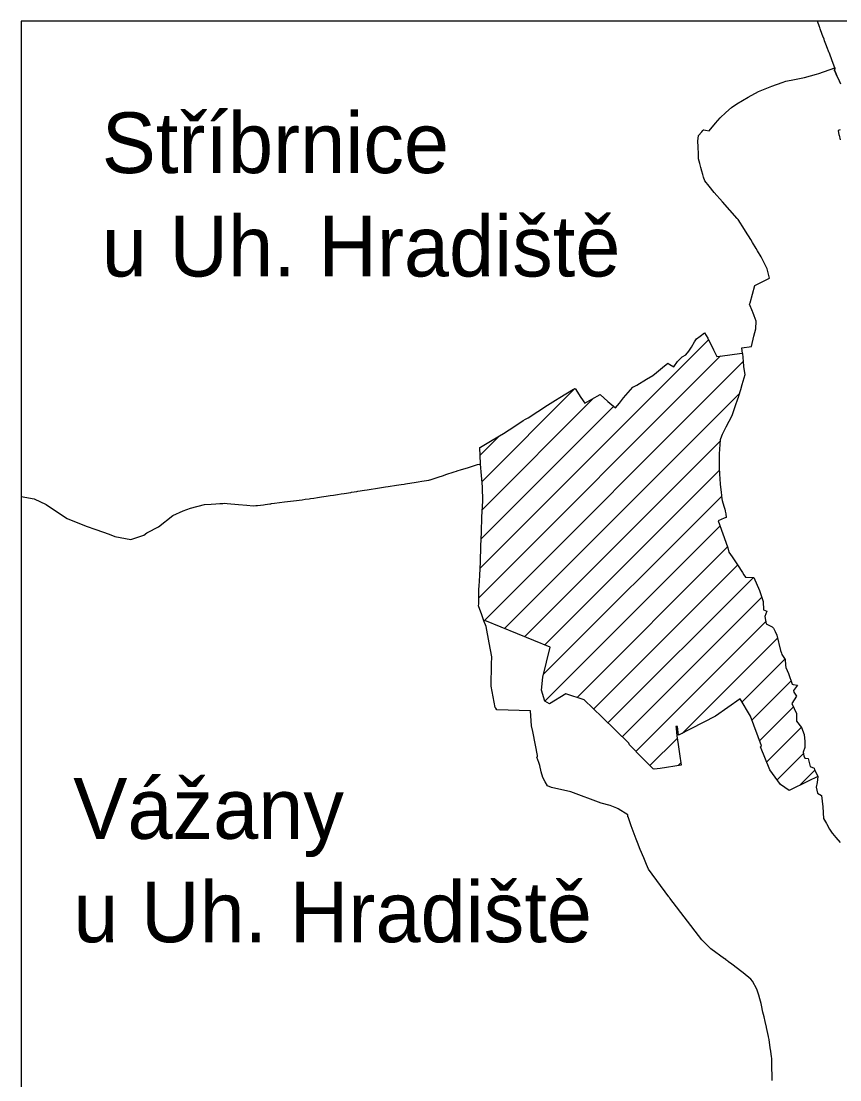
# Model space of a CAD drawing. Extents: x -552716 to -540720, y -1192685 to -1177912.
# Drawn here: x -549696 to -547852, y -1183546 to -1181162 of the extents above; entities that cross this region are included whole.
import ezdxf

# ---------------------------------------------------------------- set-up
doc = ezdxf.new("R2010")
doc.units = 0
for name, color, linetype in [('Default', 7, 'Continuous'), ('Vrstva 1', 7, 'Continuous'), ('Vrstva 2', 7, 'Continuous'), ('Vrstva 60', 7, 'Continuous')]:
    doc.layers.add(name, color=color, linetype=linetype)

msp = doc.modelspace()

# ---------------------------------------------------------------- linework, layer by layer
at = {"layer": 'Default'}
msp.add_lwpolyline([(-547901.8, -1182862.6), (-547923.2, -1182873.4), (-547966, -1182893.9), (-547985.6, -1182880.7), (-548010, -1182847.4), (-548031.1, -1182795.7), (-548028.8, -1182793.3), (-548053.4, -1182726.7), (-548076.4, -1182687.9), (-548132.3, -1182726.7), (-548215.2, -1182769.8), (-548218.1, -1182749.8), (-548221.7, -1182750.2), (-548221, -1182754.5), (-548219.1, -1182770.9), (-548216.5, -1182790.8), (-548213.3, -1182811.2), (-548209.2, -1182837.1), (-548256.6, -1182844.3), (-548270.4, -1182846.4), (-548272.9, -1182845), (-548301.7, -1182816.4), (-548320, -1182797.1), (-548326, -1182791.2), (-548327.3, -1182787.7), (-548387.7, -1182728.9), (-548427.9, -1182689.6), (-548469.4, -1182676.1), (-548506.2, -1182699.2), (-548516.9, -1182692.6), (-548523.7, -1182668.5), (-548521.4, -1182638.6), (-548504.5, -1182571.2), (-548651.4, -1182511.1), (-548653.6, -1182512)], dxfattribs=at)
at = {"layer": 'Vrstva 1'}
for p, q in [((-548174.9, -1181877), (-548166.9, -1181870.7)), ((-548166.9, -1181870.7), (-548156.9, -1181863.4)), ((-548156.9, -1181863.4), (-548149.3, -1181875.6)), ((-548186.4, -1181895.9), (-548179.2, -1181883.6)), ((-548179.2, -1181883.6), (-548174.9, -1181877)), ((-548149.3, -1181875.6), (-548136.5, -1181901.7)), ((-548217.8, -1181927.7), (-548207.2, -1181917.2)), ((-548207.2, -1181917.2), (-548199.2, -1181912.8)), ((-548199.2, -1181912.8), (-548192.1, -1181904.8)), ((-548192.1, -1181904.8), (-548186.4, -1181895.9)), ((-548136.5, -1181901.7), (-548129.2, -1181916.9)), ((-548129.2, -1181916.9), (-548121.7, -1181915.7)), ((-548121.7, -1181915.7), (-548073, -1181909.6)), ((-548073, -1181909.6), (-548071.3, -1181910)), ((-548071.3, -1181910), (-548069.8, -1181927.9)), ((-548265.3, -1181952.9), (-548251.9, -1181941.4)), ((-548251.9, -1181941.4), (-548239.4, -1181931.7)), ((-548239.4, -1181931.7), (-548235, -1181934.5)), ((-548235, -1181934.5), (-548226.1, -1181940.1)), ((-548226.1, -1181940.1), (-548217.8, -1181927.7)), ((-548069.8, -1181927.9), (-548068.9, -1181939.1)), ((-548068.9, -1181939.1), (-548066.3, -1181958.3)), ((-548287.2, -1181967.9), (-548273.5, -1181959.3)), ((-548273.5, -1181959.3), (-548265.3, -1181952.9)), ((-548066.3, -1181958.3), (-548072.7, -1181980.3)), ((-548451.7, -1181990.3), (-548448.3, -1181988.9)), ((-548448.3, -1181988.9), (-548435.2, -1182008.9)), ((-548329.1, -1181998), (-548318.1, -1181986.2)), ((-548318.1, -1181986.2), (-548309.3, -1181981.1)), ((-548309.3, -1181981.1), (-548287.2, -1181967.9)), ((-548072.7, -1181980.3), (-548076.1, -1181991.8)), ((-548492.4, -1182015.1), (-548482.7, -1182009.4)), ((-548482.7, -1182009.4), (-548469.2, -1182000.9)), ((-548469.2, -1182000.9), (-548451.7, -1181990.3)), ((-548435.2, -1182008.9), (-548426.1, -1182021.7)), ((-548426.1, -1182021.7), (-548410.5, -1182012.8)), ((-548410.5, -1182012.8), (-548391.6, -1182002.5)), ((-548391.6, -1182002.5), (-548374.7, -1182018.1)), ((-548348.6, -1182021.7), (-548339.1, -1182009.7)), ((-548339.1, -1182009.7), (-548329.1, -1181998)), ((-548082.5, -1182013), (-548087.6, -1182027.9)), ((-548081.1, -1182008.9), (-548082.5, -1182013)), ((-548080.3, -1182006.3), (-548081.1, -1182008.9)), ((-548076.1, -1181991.8), (-548080.3, -1182006.3)), ((-548532.2, -1182040.6), (-548510.7, -1182026.7)), ((-548510.7, -1182026.7), (-548492.4, -1182015.1)), ((-548374.7, -1182018.1), (-548357.4, -1182032.7)), ((-548357.4, -1182032.7), (-548348.6, -1182021.7)), ((-548087.6, -1182027.9), (-548095.3, -1182050.1)), ((-548579.7, -1182070.6), (-548565.1, -1182060.7)), ((-548565.1, -1182060.7), (-548559.8, -1182057.8)), ((-548559.8, -1182057.8), (-548553.8, -1182055)), ((-548553.8, -1182055), (-548532.2, -1182040.6)), ((-548095.3, -1182050.1), (-548108.9, -1182076.1)), ((-548609.9, -1182090.1), (-548597.1, -1182082.1)), ((-548597.1, -1182082.1), (-548579.7, -1182070.6)), ((-548109.6, -1182077.6), (-548117.3, -1182092.2)), ((-548108.9, -1182076.1), (-548109.6, -1182077.6)), ((-548661.6, -1182120.6), (-548639.3, -1182107.7)), ((-548639.3, -1182107.7), (-548618.3, -1182095.2)), ((-548618.3, -1182095.2), (-548609.9, -1182090.1)), ((-548121.6, -1182104.4), (-548123.7, -1182136.3)), ((-548120.8, -1182102.1), (-548121.6, -1182104.4)), ((-548117.3, -1182092.2), (-548120.8, -1182102.1)), ((-548663.3, -1182121.6), (-548661.6, -1182120.6)), ((-548661.5, -1182158.2), (-548663.3, -1182121.6)), ((-548123.7, -1182136.3), (-548123.7, -1182137.4)), ((-548123.7, -1182137.4), (-548123.6, -1182165.3)), ((-548661.4, -1182159.5), (-548661.5, -1182158.2)), ((-548656.7, -1182210.4), (-548661.4, -1182159.5)), ((-548123.6, -1182165.3), (-548123.6, -1182166.5)), ((-548123.6, -1182166.5), (-548122.9, -1182182.4)), ((-548122.9, -1182182.4), (-548122.4, -1182191.2)), ((-548122.4, -1182191.2), (-548121.5, -1182205.4)), ((-548656.3, -1182242.9), (-548656.7, -1182210.4)), ((-548121.5, -1182205.4), (-548119.6, -1182222.6)), ((-548119.6, -1182222.6), (-548118, -1182237.4)), ((-548658.2, -1182278.1), (-548656.3, -1182242.9)), ((-548118, -1182237.4), (-548117.1, -1182240.7)), ((-548117.1, -1182240.7), (-548113.7, -1182254.2)), ((-548113.7, -1182254.2), (-548111.5, -1182260.5)), ((-548111.5, -1182260.5), (-548110.5, -1182264)), ((-548110.5, -1182264), (-548110.1, -1182265.3)), ((-548110.1, -1182265.3), (-548109.2, -1182270.8)), ((-548109.2, -1182270.8), (-548107.8, -1182279.1)), ((-548659, -1182312.3), (-548658.2, -1182278.1)), ((-548112.4, -1182281.1), (-548125.8, -1182286.7)), ((-548125.8, -1182286.7), (-548105.2, -1182345.6)), ((-548107.8, -1182279.1), (-548112.4, -1182281.1)), ((-548660.4, -1182344), (-548659, -1182312.3)), ((-548661.7, -1182379.5), (-548660.4, -1182344)), ((-548105.2, -1182345.6), (-548104.7, -1182347.3)), ((-548104.7, -1182347.3), (-548101.8, -1182357.4)), ((-548101.8, -1182357.4), (-548094.7, -1182368.1)), ((-548094.7, -1182368.1), (-548082.8, -1182386.3)), ((-548663.3, -1182410.2), (-548661.7, -1182379.5)), ((-548082.8, -1182386.3), (-548071.6, -1182403.4)), ((-548664.8, -1182433.7), (-548663.3, -1182410.2)), ((-548071.6, -1182403.4), (-548068.2, -1182408.4)), ((-548068.2, -1182408.4), (-548064.5, -1182413.6)), ((-548064.5, -1182413.6), (-548045.5, -1182414.5)), ((-548045.5, -1182414.5), (-548032.9, -1182443.7)), ((-548665.1, -1182474.1), (-548664.9, -1182440.9)), ((-548664.9, -1182440.9), (-548664.8, -1182433.7)), ((-548032.9, -1182443.7), (-548024.6, -1182468.7)), ((-548665.6, -1182478.6), (-548665.1, -1182474.1)), ((-548658.8, -1182498.9), (-548665.6, -1182478.6)), ((-548024.6, -1182468.7), (-548024.1, -1182487.1)), ((-548024.1, -1182487.1), (-548016.9, -1182490.4)), ((-548016.9, -1182490.4), (-548021, -1182502.3)), ((-548653.6, -1182512), (-548658.8, -1182498.9)), ((-548648.7, -1182524.6), (-548653.6, -1182512)), ((-548021, -1182502.3), (-548018.1, -1182518.6)), ((-548641.7, -1182561.3), (-548648.7, -1182524.6)), ((-548018.1, -1182518.6), (-548004.5, -1182525.3)), ((-548004.5, -1182525.3), (-548001.6, -1182528.4)), ((-548001.6, -1182528.4), (-547997.4, -1182536.4)), ((-547997.4, -1182536.4), (-547994.1, -1182544)), ((-548635.9, -1182593.4), (-548641.7, -1182561.3)), ((-547994.1, -1182544), (-547986.1, -1182579.1)), ((-547986.1, -1182579.1), (-547983.8, -1182584.6)), ((-547983.8, -1182584.6), (-547982.5, -1182587.9)), ((-548637.6, -1182658.9), (-548636.5, -1182609.9)), ((-548636.5, -1182609.9), (-548635.9, -1182593.4)), ((-547982.5, -1182587.9), (-547974.9, -1182598.9)), ((-547974.9, -1182598.9), (-547974.6, -1182612)), ((-547974.6, -1182612), (-547973.4, -1182617.2)), ((-547973.4, -1182617.2), (-547967.7, -1182630.5)), ((-547967.7, -1182630.5), (-547959.2, -1182654.4)), ((-547959.2, -1182654.4), (-547956.9, -1182655.4)), ((-547956.9, -1182655.4), (-547947.5, -1182656.8)), ((-547947.5, -1182656.8), (-547956.1, -1182669.3)), ((-548628.2, -1182707.3), (-548637.6, -1182658.9)), ((-547956.1, -1182669.3), (-547955.4, -1182673)), ((-547955.4, -1182673), (-547949.7, -1182681.7)), ((-547949.7, -1182681.7), (-547960.2, -1182698)), ((-547960.2, -1182698), (-547949.5, -1182721)), ((-548627, -1182709.1), (-548628.2, -1182707.3)), ((-548624.7, -1182712.5), (-548627, -1182709.1)), ((-548549.2, -1182715.1), (-548624.7, -1182712.5)), ((-548546.3, -1182748.6), (-548549.2, -1182715.1)), ((-547949.5, -1182721), (-547950, -1182738.2)), ((-548543.8, -1182761.5), (-548546.3, -1182748.6)), ((-547950, -1182738.2), (-547938.6, -1182752.1)), ((-547938.6, -1182752.1), (-547932.4, -1182767.7)), ((-548537.8, -1182792.2), (-548543.8, -1182761.5)), ((-547932.4, -1182767.7), (-547930.7, -1182783.5)), ((-548533.2, -1182815.6), (-548537.8, -1182792.2)), ((-547930.6, -1182797.2), (-547934.8, -1182807.6)), ((-547930.7, -1182783.5), (-547930.6, -1182797.2)), ((-548534.4, -1182819), (-548532.8, -1182817.7)), ((-548529.8, -1182831.3), (-548534.4, -1182819)), ((-548532.8, -1182817.7), (-548533.2, -1182815.6)), ((-547934.8, -1182807.6), (-547932.9, -1182816.1)), ((-547932.9, -1182816.1), (-547931, -1182821.2)), ((-547931, -1182821.2), (-547923.5, -1182822.4)), ((-547923.5, -1182822.4), (-547918.7, -1182840.1)), ((-548528.1, -1182838.1), (-548529.8, -1182831.3)), ((-548524.5, -1182852.3), (-548528.1, -1182838.1)), ((-547918.7, -1182840.1), (-547909.7, -1182843.6)), ((-547909.7, -1182843.6), (-547909.3, -1182846.6)), ((-547909.3, -1182846.6), (-547901.8, -1182862.6)), ((-548521.2, -1182865.1), (-548524.5, -1182852.3)), ((-548515.9, -1182874.6), (-548521.2, -1182865.1)), ((-547901.8, -1182862.6), (-547903.4, -1182876)), ((-548510.8, -1182883.7), (-548515.9, -1182874.6)), ((-548501.2, -1182887.3), (-548510.8, -1182883.7)), ((-548458, -1182897.5), (-548501.2, -1182887.3)), ((-547903.4, -1182876), (-547905.3, -1182886.7)), ((-547905.3, -1182886.7), (-547902.5, -1182900.1)), ((-548389.9, -1182922.6), (-548458, -1182897.5)), ((-547902.5, -1182900.1), (-547893.5, -1182905.3)), ((-547893.5, -1182905.3), (-547890.7, -1182930.9)), ((-548369.1, -1182928.1), (-548389.9, -1182922.6)), ((-548354.7, -1182933.8), (-548369.1, -1182928.1)), ((-548351.3, -1182935.1), (-548354.7, -1182933.8)), ((-548329.4, -1182948.9), (-548351.3, -1182935.1)), ((-547890.7, -1182930.9), (-547888.6, -1182957)), ((-548329.4, -1182953.3), (-548329.4, -1182948.9)), ((-548329.2, -1182953.8), (-548329.4, -1182953.3)), ((-548322, -1182973.8), (-548329.2, -1182953.8)), ((-547888.6, -1182957), (-547882.4, -1182968.1)), ((-548315.5, -1182991.8), (-548322, -1182973.8)), ((-547882.4, -1182968.1), (-547881.4, -1182969.9)), ((-547881.4, -1182969.9), (-547875.1, -1182981.3)), ((-547875.1, -1182981.3), (-547869.5, -1182990)), ((-547869.5, -1182990), (-547868.6, -1182991.2)), ((-547868.6, -1182991.2), (-547861.3, -1183000.1)), ((-548311.1, -1183004), (-548315.5, -1182991.8)), ((-548308.2, -1183010.9), (-548311.1, -1183004)), ((-548301.5, -1183027), (-548308.2, -1183010.9)), ((-547861.3, -1183000.1), (-547851.6, -1183011.3)), ((-548293.9, -1183045.5), (-548301.5, -1183027)), ((-548287.6, -1183060.6), (-548293.9, -1183045.5)), ((-548283.2, -1183071.2), (-548287.6, -1183060.6)), ((-548237.1, -1183133.7), (-548283.2, -1183071.2)), ((-548235.9, -1183135.3), (-548237.1, -1183133.7)), ((-548235, -1183136.5), (-548235.9, -1183135.3)), ((-548162.7, -1183230.2), (-548235, -1183136.5)), ((-548142.7, -1183251), (-548162.7, -1183230.2)), ((-548111.8, -1183272.9), (-548142.7, -1183251)), ((-548111.2, -1183273.3), (-548111.8, -1183272.9)), ((-548109.2, -1183274.9), (-548111.2, -1183273.3)), ((-548108.9, -1183275.1), (-548109.2, -1183274.9)), ((-548104.6, -1183278.3), (-548108.9, -1183275.1)), ((-548103.4, -1183279.3), (-548104.6, -1183278.3)), ((-548102.7, -1183279.8), (-548103.4, -1183279.3)), ((-548095.2, -1183285.5), (-548102.7, -1183279.8)), ((-548072.9, -1183302.4), (-548095.2, -1183285.5)), ((-548069.6, -1183304.9), (-548072.9, -1183302.4)), ((-548052.8, -1183319.2), (-548069.6, -1183304.9)), ((-548048.8, -1183323.6), (-548052.8, -1183319.2)), ((-548039.2, -1183341.9), (-548048.8, -1183323.6)), ((-548036.2, -1183350.4), (-548039.2, -1183341.9)), ((-548034.5, -1183355.3), (-548036.2, -1183350.4)), ((-548032.3, -1183363.6), (-548034.5, -1183355.3)), ((-548029.5, -1183373.9), (-548032.3, -1183363.6)), ((-548028.8, -1183377.2), (-548029.5, -1183373.9)), ((-548025.2, -1183393.2), (-548028.8, -1183377.2)), ((-548022.7, -1183404), (-548025.2, -1183393.2)), ((-548020.4, -1183414.1), (-548022.7, -1183404)), ((-548017.5, -1183426.9), (-548020.4, -1183414.1)), ((-548017.3, -1183427.8), (-548017.5, -1183426.9)), ((-548014.2, -1183441.2), (-548017.3, -1183427.8)), ((-548012.7, -1183448.1), (-548014.2, -1183441.2)), ((-548012.6, -1183448.5), (-548012.7, -1183448.1)), ((-548011.5, -1183455.2), (-548012.6, -1183448.5)), ((-548008.8, -1183473.5), (-548011.5, -1183455.2)), ((-548007.6, -1183481.3), (-548008.8, -1183473.5)), ((-548005.7, -1183493.8), (-548007.6, -1183481.3)), ((-548005.6, -1183497), (-548005.7, -1183493.8)), ((-548005.5, -1183502.1), (-548005.6, -1183497)), ((-548005.3, -1183508), (-548005.5, -1183502.1)), ((-548005, -1183520.9), (-548005.3, -1183508)), ((-548004.7, -1183533.8), (-548005, -1183520.9)), ((-548004.4, -1183547), (-548004.7, -1183533.8))]:
    msp.add_line(p, q, dxfattribs=at)
for points in [[(-547852.6, -1181297.8), (-547853.1, -1181296.8), (-547857.4, -1181287.9), (-547859.1, -1181284.5), (-547863.6, -1181273.6), (-547863.8, -1181273.3), (-547863.1, -1181266.9), (-547869.1, -1181250.8), (-547875.6, -1181233.7), (-547876, -1181232.7), (-547881.1, -1181219.4), (-547882, -1181217), (-547886.3, -1181206), (-547887.7, -1181202.3), (-547890.3, -1181195.1), (-547891.7, -1181191.4), (-547896.2, -1181178.9), (-547897.3, -1181175.8), (-547897.9, -1181174.1), (-547902.3, -1181161.6)], [(-548071.3, -1181910), (-548072.8, -1181897), (-548051.2, -1181894.5), (-548045.7, -1181871.2), (-548041.4, -1181854.8), (-548040.7, -1181837.4), (-548044.7, -1181825.4), (-548048.1, -1181817), (-548048.5, -1181815.8), (-548055.5, -1181799.2), (-548054.9, -1181797.4), (-548054.4, -1181795.6), (-548043.4, -1181756.9), (-548034.7, -1181752.4), (-548024.3, -1181747.1), (-548018.3, -1181744.2), (-548010.5, -1181740.3), (-548015.5, -1181719.4), (-548029.5, -1181692.4), (-548037.5, -1181678.8), (-548040.5, -1181673.8), (-548048.9, -1181659.8), (-548052.9, -1181653.2), (-548064.5, -1181634.6), (-548067.1, -1181630.5), (-548081.2, -1181608.2), (-548083.2, -1181605.9), (-548116.2, -1181568.6), (-548135.4, -1181547.1), (-548146.6, -1181533.2), (-548156.4, -1181521), (-548158.9, -1181512.6), (-548160.4, -1181507.2), (-548162.7, -1181499.4), (-548165.2, -1181491.1), (-548167.6, -1181481.9), (-548170.2, -1181472), (-548170.3, -1181471.4), (-548170.8, -1181460.9), (-548170.8, -1181460.6), (-548171.5, -1181445.4), (-548171.5, -1181444.3), (-548171.6, -1181432.2), (-548170.7, -1181419.4), (-548163.2, -1181410.8), (-548160.8, -1181407.9), (-548159.2, -1181406), (-548158.7, -1181406.1), (-548154.6, -1181406.9), (-548146.1, -1181408.5), (-548132, -1181391.1), (-548121.3, -1181379.2), (-548109.2, -1181367.4), (-548096.2, -1181356.4), (-548083.8, -1181348.1), (-548071.3, -1181340.1), (-548058.2, -1181333), (-548035.2, -1181320.3), (-548004.9, -1181308), (-547982.3, -1181299.8), (-547973.7, -1181296.8), (-547953.9, -1181293.1), (-547931.5, -1181288.4), (-547904.7, -1181280.9), (-547899.5, -1181279.5), (-547863.1, -1181266.9)], [(-547863.1, -1181266.9), (-547863.8, -1181273.3), (-547863.6, -1181273.6), (-547859.1, -1181284.5), (-547857.4, -1181287.9), (-547853.1, -1181296.8), (-547852.6, -1181297.8), (-547850.4, -1181302.4)], [(-547851.3, -1181406.3), (-547856, -1181408), (-547854, -1181417.9), (-547853.8, -1181418.5), (-547851.7, -1181429.1)], [(-549696, -1182232.4), (-549666.8, -1182237.6), (-549639.8, -1182249.8), (-549627.5, -1182258), (-549592.1, -1182281.8), (-549550, -1182298.9), (-549527.9, -1182306.7), (-549498.2, -1182317.2), (-549485.1, -1182321.8), (-549449.4, -1182328.7), (-549426.4, -1182321.5), (-549419.8, -1182319.4), (-549413.3, -1182313.7), (-549411.8, -1182312.9), (-549386.4, -1182300.4), (-549354.3, -1182275.1), (-549331.5, -1182264.6), (-549314.4, -1182258.6), (-549283.4, -1182250.3), (-549268.3, -1182249.3), (-549257.8, -1182248.6), (-549248.9, -1182248.1), (-549241.5, -1182247.6), (-549237.2, -1182247.4), (-549231.9, -1182247.8), (-549206.8, -1182249.9), (-549187.4, -1182251.8), (-549173.8, -1182253.2), (-549167.2, -1182252.4), (-549163.8, -1182252), (-549150, -1182250.5), (-549146.7, -1182250.1), (-549136.3, -1182248.7), (-549135, -1182248.6), (-549133.6, -1182248.4), (-549132.4, -1182248.2), (-549125.7, -1182247.4), (-549102.6, -1182244.4), (-549082.5, -1182241.8), (-549063.2, -1182239.2), (-549056, -1182238.3), (-549047.7, -1182237.2), (-549044.2, -1182236.7), (-549037.2, -1182235.6), (-549028.7, -1182234.3), (-549024, -1182233.6), (-549019.5, -1182232.9), (-549009.4, -1182231.4), (-549000.4, -1182230), (-548992.4, -1182228.8), (-548983.8, -1182227.5), (-548975.5, -1182226.2), (-548968.3, -1182225.1), (-548953.2, -1182222.8), (-548952.2, -1182222.6), (-548940.3, -1182220.8), (-548937.5, -1182220.4), (-548922.8, -1182218.1), (-548916.8, -1182217.2), (-548907.5, -1182215.7), (-548898.1, -1182214.2), (-548888.8, -1182212.8), (-548875.1, -1182210.6), (-548869.8, -1182209.8), (-548850.8, -1182206.8), (-548840, -1182205.1), (-548833.7, -1182204.1), (-548830.7, -1182203.7), (-548815.8, -1182201.3), (-548810.9, -1182200.6), (-548802.2, -1182199.2), (-548793.3, -1182197.8), (-548778.1, -1182195.4), (-548775.9, -1182194.7), (-548774.9, -1182194.4), (-548754.7, -1182187.6), (-548747.2, -1182185.2), (-548745, -1182184.4), (-548739.6, -1182182.6), (-548721.1, -1182176.5), (-548715.7, -1182174.7), (-548713.9, -1182174.1)], [(-548713.9, -1182174.1), (-548704.1, -1182171.1), (-548691, -1182167.2), (-548675.3, -1182162.4), (-548668, -1182160.2), (-548663.4, -1182158.9), (-548661.4, -1182159.5)]]:
    msp.add_lwpolyline(points, dxfattribs=at)
at = {"layer": 'Vrstva 2'}
for p, q in [((-548662.4, -1182393.6), (-548147.7, -1181878.9)), ((-548665, -1182459.9), (-548120.7, -1181915.6)), ((-548653.5, -1182512), (-548069.8, -1181928.3)), ((-548657.8, -1182198.1), (-548448.8, -1181989.1)), ((-548657.3, -1182261.2), (-548406.9, -1182010.8)), ((-548607.1, -1182529.2), (-548078.8, -1182000.9)), ((-548659.7, -1182327.2), (-548361.6, -1182029.1)), ((-548662.5, -1182139.1), (-548619, -1182095.6)), ((-548561.9, -1182547.7), (-548121.8, -1182107.6)), ((-548516.7, -1182566.1), (-548123.3, -1182172.7)), ((-548520.1, -1182633.1), (-548118.6, -1182231.7)), ((-548516.3, -1182693), (-548121.7, -1182298.4)), ((-548444.1, -1182684.4), (-548105.2, -1182345.5)), ((-548406.5, -1182710.5), (-548082.6, -1182386.6)), ((-548374.3, -1182741.9), (-548046.8, -1182414.4)), ((-548342.1, -1182773.3), (-548027.8, -1182459.1)), ((-548311.3, -1182806.2), (-548019, -1182513.8)), ((-548207, -1182765.6), (-547992.5, -1182551)), ((-548072.4, -1182694.6), (-547975.6, -1182597.8)), ((-548050, -1182735.8), (-547961.7, -1182647.5)), ((-548032.9, -1182782.3), (-547956.5, -1182705.9)), ((-548017, -1182830.1), (-547938.8, -1182751.8)), ((-548279.7, -1182838.2), (-548218.4, -1182776.9)), ((-547993.4, -1182870.1), (-547934.1, -1182810.8)), ((-548216, -1182838.1), (-548210, -1182832.1)), ((-547942.1, -1182882.4), (-547908.3, -1182848.7))]:
    msp.add_line(p, q, dxfattribs=at)
at = {"layer": 'Vrstva 60'}
msp.add_lwpolyline([(-543896.1, -1181161.6), (-549696, -1181161.6), (-549696, -1188366.4), (-543896.1, -1188366.4)], close=True, dxfattribs=at)

# ---------------------------------------------------------------- texts
at = {"layer": 'Vrstva 1'}
for s, height, p in [('Stříbrnice', 136.69, (-549514.5, -1181503.8)), ('u Uh. Hradiště', 136.688, (-549514.5, -1181736.6)), ('Vážany', 136.69, (-549578.7, -1183003)), ('u Uh. Hradiště', 136.688, (-549578.7, -1183235.9))]:
    msp.add_text(s, height=height, dxfattribs=at).set_placement(p)

doc.saveas('drawing.dxf')
